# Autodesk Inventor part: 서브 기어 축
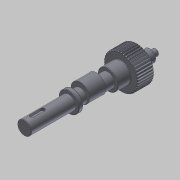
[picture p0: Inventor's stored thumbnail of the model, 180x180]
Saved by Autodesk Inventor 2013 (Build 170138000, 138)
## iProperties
Created: 2018-12
Part Number: 서브 기어 축
Material: 강철, 연강
Document SubType Name: Modeling
Designer: mduedu
Categories: <?xml version="1.0" encoding="UTF-16"?> <MemberInstance><Categories><FamilyTemplate><FamilyTemplateParameter ValueType="xs:double" Id="1" ObjectReferenceKey="da
Density: 7.86 g/cm^3
Mass: 514.749 g
Surface Area: 160.365 cm^2
Volume: 65.4897 cm^3
Author: mduedu
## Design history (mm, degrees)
sketch "Sketch1"
  geometry: C1 r 21.3 at (0, 0)
  constraints: 1 centre point
  dimensions: "d0" = 42.6 diameter of C1 (= da_da)
extrude "Extrusion1" new body sketch "Sketch1" distance "d1" = 20 (= da_b); taper "d2" = 0 deg
workplane "Work Plane2"
sketch "Sketch2"
  geometry: C1 r 21.3 at (0, 0) reference; C2 r 20.5 at (0, 0)
  constraints: 1 centre point, 1 coincident
  dimensions: "d3" = 41 diameter of C2 (= da_dw)
feature "피치 지름" sketch "Sketch2" dims "d4" = 10, "d5" = 0
workplane "Work Plane8"
workplane "Work Plane9"
chamfer "모따기1" distance "d49" = 1; stored, may be unused: second distance "d50" = 2, angle "d51" = 45 deg
sketch "스케치3"
  geometry: C1 r 12.5 at (0, 0); 1 further point
  constraints: 1 centre point, 1 coincident
  dimensions: "d52" = 25 diameter of C1
extrude "돌출2" join sketch "스케치3" distance "d53" = 16; taper "d54" = 0 deg
sketch "스케치4"
  geometry: C1 r 8.5 at (0, 0); 1 further point
  constraints: 1 centre point, 1 coincident
  dimensions: "d55" = 17 diameter of C1
extrude "돌출3" join sketch "스케치4" distance "d56" = 103; taper "d57" = 0 deg
sketch "스케치5"
  geometry: C1 r 7.5 at (0, 0); 1 further point
  constraints: 1 centre point, 1 coincident
  dimensions: "d58" = 15 diameter of C1
extrude "돌출4" join sketch "스케치5" distance "d59" = 16; taper "d60" = 0 deg
sketch "스케치6"
  geometry: C1 r 4 at (0, 0); 1 further point
  constraints: 1 centre point, 1 coincident
  dimensions: "d61" = 8 diameter of C1
extrude "돌출5" join sketch "스케치6" distance "d62" = 7; taper "d63" = 0 deg
chamfer "모따기2" distance "d64" = 0.5; stored, may be unused: second distance "d65" = 2, angle "d66" = 45 deg
fillet "모깎기1" dims "d67" = 0.5
feature "스퍼 기어" dims "da_b" = 20, "da_d" = 41, "da_aw" = 31, "da_da" = 42.6, "da_df" = 39.086, "da_dw" = 41, angle "da_beta" = 0 deg, "da_lefttooth" = 0, "da_righttooth" = 0
node "작업 평면11"
sketch "스케치7"
  geometry: C1 r 11.5 at (0, 3); C2 r 8.5 at (0, 0) reference; 1 further point
  constraints: 1 centre point, 1 tangent, 1 vertical alignment
  dimensions: "d69" = 3 distance of point (0, 0) C1.centre; "d70" = 23 diameter of C1 (derived)
extrude "돌출6" join sketch "스케치7" stored distance "d71" = 20; taper "d72" = 0 deg
node "작업 평면12"
sketch "스케치8"
  geometry: C1 r 12.5 at (0, 0) reference; C2 r 12.5 at (0, 0) reference; 1 further point
extrude "돌출7" join sketch "스케치8" distance "d74" = 5; taper "d75" = 0 deg
chamfer "모따기3" distance "d76" = 0.5; stored, may be unused: second distance "d77" = 2, angle "d78" = 45 deg
sketch "스케치9"
  geometry: L1 (-8, 139)-(8, 139) reference; L2 (0, 139)-(0, 0); L3 (-8.5, 84)-(-8.5, 138.5) reference; L4 (-8.5, 115)-(0, 115); L5 (-8.5, 115)-(-8.5, 113.5); L6 (-8.5, 113.5)-(-7, 115); L7 (-7, 115)-(-8.5, 115)
  constraints: 10 end point, 4 point on line, 2 perpendicular, 1 collinear, 1 midpoint
  dimensions: "d79" = 24 distance between parallel lines of L4 L1; "d80" = 3 diameter of L5.end L4; "d81" = 45 deg angle of L6 L3
revolve "회전1" sketch "스케치9" stored, may be unused: angle "d82" = 90 deg
sketch "스케치10"
  geometry: L1 (-8.5, 116.5)-(-7, 115) reference; L2 (-8.5, 113.5)-(-7, 115) reference; 2 further points
  constraints: 1 coincident
node "작업점1"
node "작업 평면13"
sketch "스케치11"
  geometry: L1 (-2.5, 93.5)-(-2.5, 80.5); L2 (2.5, 80.5)-(2.5, 93.5); L3 (-8, 103)-(8, 103) reference; A1 r 2.5 centre (0, 93.5) between (2.5, 93.5) and (-2.5, 93.5); A2 r 2.5 centre (0, 80.5) between (-2.5, 80.5) and (2.5, 80.5); 1 further point
  constraints: 4 end point, 4 point on circle, 4 tangent, 2 centre point, 2 vertical alignment, 1 parallel
  dimensions: "d83" = 7 distance edge to line of A1 L3; "d84" = 18 dimension on A2 A1; "d85" = 5 distance between parallel lines of L1 L2
extrude "돌출8" cut sketch "스케치11" distance "d86" = 3; taper "d87" = 0 deg
sketch "스케치12" dims "d88" = 32
  geometry: C1 r 0.5 at (0, -16); 2 further points
  constraints: 2 vertical alignment, 1 centre point, 1 coincident, 2 other
  dimensions: "d89" = 1 diameter of C1
extrude "돌출9" join sketch "스케치12" distance "d90" = 0.3; taper "d91" = 0 deg
sketch "스케치13"
  geometry: C1 r 11.5 at (0, 3) reference; 1 further point
  node "절단 모서리 투영1"
body "Solid1"
body "Srf1"
node "투영된 루프1"
other parameters: "d16" = 31 (= da_aw), "d17" = 0, "d34" = 0.76624 (computed from da_z), "d39" = 0, "d41" = 0, "d43" = 31 (= da_aw), "d46" = 31 (= da_aw), "d47" = 0, "d48" = 0, "d68" = 24, "d73" = 48
